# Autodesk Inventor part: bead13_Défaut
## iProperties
Shininess: 64.0
Length Units: 11269
Angle Units: 11279
Time Units: 11290
Mass Units: 11283
Length Display Precision: 3
Angle Display Precision: 2
Compacted: True
Part Number: bead13_Défaut
Document SubType Name: Modeling
Created: 2006-01
Material: Par défaut
Designer: Fricot
Density: 0.0
Volumn: 0.0
Area: 0.0
PropertySet Name: Model Information
Control State: 0
Master: False
Checked Out: False
Author: Fricot
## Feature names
1. Base1
